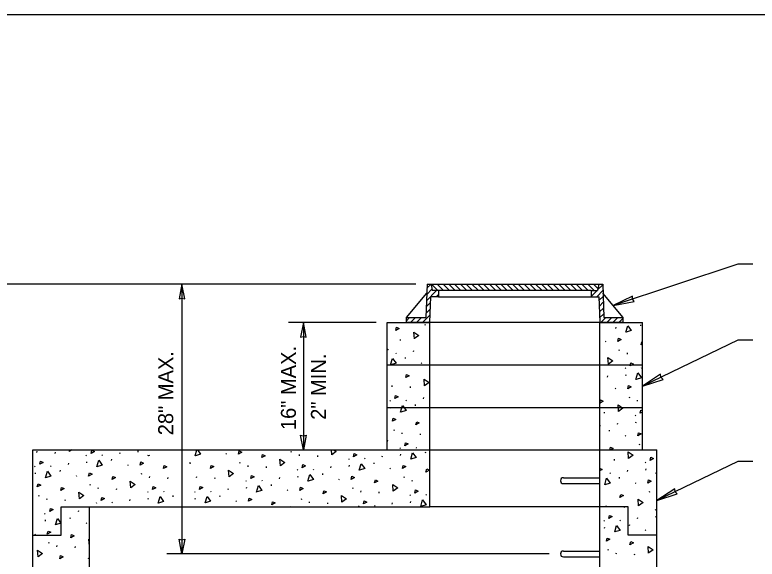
# Model space of a CAD drawing. Extents: x 99862 to 103151, y 100000 to 102076.
# Drawn here: x 100585 to 101377, y 101495 to 102076 of the extents above; entities that cross this region are included whole.
import ezdxf

# ---------------------------------------------------------------- set-up
doc = ezdxf.new("R2010")
doc.units = 0
for name, color, linetype in [('Level 1', 7, 'Continuous'), ('Level 15', 7, 'Continuous'), ('Level 16', 7, 'Continuous'), ('Level 17', 7, 'Continuous'), ('Level 18', 7, 'Continuous'), ('Level 20', 7, 'Continuous')]:
    doc.layers.add(name, color=color, linetype=linetype)

msp = doc.modelspace()

# ---------------------------------------------------------------- linework, layer by layer
at = {"layer": 'Level 1'}
for p, q in [((101024.66, 101788.47), (101023.36, 101752.82)), ((101024.19, 101777.48), (101029.83, 101783.11)), ((101024.46, 101784.09), (101028.81, 101788.47)), ((101024.66, 101788.47), (101030.11, 101788.47)), ((101028.86, 101788.47), (101030.11, 101781.67)), ((101029.31, 101788.47), (101036.1, 101781.67)), ((101030.11, 101788.47), (101207.63, 101788.47)), ((101035.48, 101788.47), (101042.27, 101781.67)), ((101041.65, 101788.47), (101048.44, 101781.67)), ((101047.82, 101788.47), (101054.62, 101781.67)), ((101053.99, 101788.47), (101060.79, 101781.67)), ((101060.16, 101788.47), (101066.96, 101781.67)), ((101066.33, 101788.47), (101073.14, 101781.67)), ((101072.5, 101788.47), (101079.31, 101781.67)), ((101078.68, 101788.47), (101085.49, 101781.67)), ((101084.85, 101788.47), (101091.66, 101781.67)), ((101091.02, 101788.47), (101097.83, 101781.67)), ((101097.2, 101788.47), (101104.01, 101781.67)), ((101103.37, 101788.47), (101110.18, 101781.67)), ((101109.55, 101788.47), (101116.35, 101781.67)), ((101115.72, 101788.47), (101122.52, 101781.67)), ((101121.89, 101788.47), (101128.69, 101781.67)), ((101128.07, 101788.47), (101134.86, 101781.67)), ((101134.24, 101788.47), (101141.03, 101781.67)), ((101140.42, 101788.47), (101147.21, 101781.67)), ((101146.59, 101788.47), (101153.38, 101781.67)), ((101152.76, 101788.47), (101159.55, 101781.67)), ((101158.94, 101788.47), (101165.73, 101781.67)), ((101165.11, 101788.47), (101171.9, 101781.67)), ((101171.29, 101788.47), (101178.08, 101781.67)), ((101177.46, 101788.47), (101184.25, 101781.67)), ((101183.63, 101788.47), (101190.42, 101781.67)), ((101189.81, 101788.47), (101196.6, 101781.67)), ((101195.98, 101788.47), (101202.77, 101781.67)), ((101202.15, 101788.47), (101206.8, 101783.83)), ((101207.63, 101788.47), (101206.41, 101781.67)), ((101206.46, 101782.23), (101211.95, 101787.67)), ((101207.63, 101788.47), (101211.91, 101788.47)), ((101211.91, 101788.47), (101213.12, 101752.82)), ((101002.58, 101752.82), (101024.25, 101778.73)), ((101023.97, 101770.81), (101034.81, 101781.67)), ((101036.96, 101781.67), (101030.11, 101781.67)), ((101034.4, 101774.91), (101036.96, 101777.38)), ((101036.96, 101781.67), (101036.96, 101774.91)), ((101199.61, 101781.67), (101036.96, 101781.67)), ((101199.61, 101781.67), (101206.41, 101781.67)), ((101199.61, 101781.67), (101199.61, 101774.91)), ((101199.61, 101775.38), (101205.89, 101781.67)), ((101205.53, 101774.91), (101212.1, 101781.52)), ((101208.23, 101771.22), (101212.33, 101775.28)), ((101233.9, 101752.82), (101212.19, 101778.73)), ((101023.73, 101764.24), (101028.34, 101768.8)), ((101027.6, 101747.75), (101028.57, 101774.91)), ((101037.05, 101774.91), (101028.57, 101774.91)), ((101036.96, 101774.91), (101199.61, 101774.91)), ((101199.61, 101774.91), (101208.13, 101774.91)), ((101209.12, 101747.75), (101208.13, 101774.91)), ((101208.46, 101765.08), (101212.56, 101769.13)), ((101023.55, 101757.61), (101028.12, 101762.19)), ((101208.65, 101758.89), (101212.8, 101762.98)), ((101002.58, 101752.82), (101023.36, 101752.82)), ((101002.58, 101747.75), (101002.58, 101752.82)), ((101002.58, 101749.47), (101006.02, 101752.82)), ((101007.27, 101747.75), (101012.41, 101752.82)), ((101013.72, 101747.75), (101018.79, 101752.82)), ((101020.15, 101747.75), (101027.83, 101755.57)), ((101208.88, 101752.78), (101213.03, 101756.79)), ((101210.33, 101747.75), (101215.4, 101752.82)), ((101213.12, 101752.82), (101233.9, 101752.82)), ((101216.7, 101747.75), (101221.79, 101752.82)), ((101223.13, 101747.75), (101228.21, 101752.82)), ((101229.48, 101747.75), (101233.9, 101752.18)), ((101233.9, 101747.75), (101233.9, 101752.82)), ((101002.58, 101747.75), (101027.6, 101747.75)), ((101026.48, 101747.75), (101027.6, 101748.92)), ((101027.6, 101747.75), (101209.12, 101747.75)), ((101209.12, 101747.75), (101233.9, 101747.75))]:
    msp.add_line(p, q, dxfattribs=at)
msp.add_lwpolyline([(99862, 99999.5), (103151, 99999.5), (103151, 102075.5), (99862, 102075.5)], close=True, dxfattribs=at)
at = {"layer": 'Level 15'}
for p, q in [((101356.07, 101809.67), (101223.05, 101765.78)), ((101372.07, 101809.67), (101356.07, 101809.67)), ((101012.66, 101788.47), (100352.49, 101788.47)), ((100763.18, 101788.47), (100763.18, 101500.81)), ((100970.21, 101747.72), (100876.72, 101747.72)), ((100892.72, 101747.72), (100892.72, 101611.69)), ((101356.07, 101728.7), (101254.43, 101679.7)), ((101372.07, 101728.7), (101356.07, 101728.7)), ((101356.07, 101599.38), (101269.59, 101557.69)), ((101372.07, 101599.38), (101356.07, 101599.38)), ((101154.85, 101500.81), (100747.18, 101500.81))]:
    msp.add_line(p, q, dxfattribs=at)
for points in [[(100763.18, 101788.47), (100760.1, 101772.75), (100763.18, 101773.48), (100766.27, 101772.75)], [(101223.05, 101765.78), (101245.66, 101770.09), (101243.72, 101772.6), (101243.79, 101775.76)], [(100892.72, 101747.72), (100889.63, 101731.99), (100892.72, 101732.72), (100895.8, 101731.99)], [(101254.43, 101679.7), (101276.29, 101686.93), (101274.04, 101689.16), (101273.7, 101692.31)], [(100892.72, 101611.69), (100889.63, 101627.42), (100892.72, 101626.69), (100895.8, 101627.42)], [(101269.59, 101557.69), (101291.45, 101564.92), (101289.2, 101567.15), (101288.86, 101570.3)], [(100763.18, 101500.81), (100760.1, 101516.54), (100763.18, 101515.81), (100766.27, 101516.54)]]:
    msp.add_lwpolyline(points, close=True, dxfattribs=at)
at = {"layer": 'Level 16'}
for p, q in [((101022.39, 101745.91), (101022.74, 101744.84)), ((101252.44, 101743.98), (101252.69, 101745.18)), ((101225.89, 101741.26), (101226.15, 101742.46)), ((100996.11, 101728.37), (100996.37, 101729.57)), ((101214.52, 101727.79), (101215.16, 101727.16)), ((100991.16, 101715.06), (100991.8, 101714.43)), ((101010.17, 101716.61), (101010.43, 101717.81)), ((101229.29, 101718.74), (101229.65, 101717.67)), ((101238.25, 101713.89), (101238.5, 101715.09)), ((101001.46, 101709.18), (101001.71, 101710.38)), ((101018.31, 101704.63), (101018.95, 101704.01)), ((101235.81, 101699.14), (101236.45, 101698.52)), ((101252.84, 101699.53), (101253.48, 101698.9)), ((101217.08, 101689.44), (101217.33, 101690.64)), ((101236.59, 101690.93), (101236.84, 101692.13)), ((100987.26, 101679.09), (100987.52, 101680.29)), ((101006.81, 101678.04), (101007.06, 101679.24)), ((101225.22, 101677.46), (101225.86, 101676.83)), ((100984.83, 101664.35), (100985.47, 101663.72)), ((101001.86, 101664.73), (101002.5, 101664.11)), ((101020.87, 101666.29), (101021.13, 101667.49)), ((101239.99, 101668.41), (101240.34, 101667.34)), ((101248.94, 101663.56), (101249.2, 101664.76)), ((100985.61, 101656.14), (100985.86, 101657.34)), ((101012.16, 101658.86), (101012.41, 101660.05)), ((101213.71, 101650.87), (101213.97, 101652.07)), ((101246.51, 101648.82), (101247.15, 101648.19)), ((101247.29, 101640.61), (101247.54, 101641.81)), ((100989.01, 101633.61), (100989.36, 101632.54)), ((101209.11, 101637.23), (101209.41, 101636.93)), ((101219.06, 101631.68), (101219.31, 101632.88)), ((101227.77, 101639.11), (101228.03, 101640.31)), ((100997.96, 101628.77), (100998.21, 101629.97)), ((101017.5, 101627.71), (101017.76, 101628.91)), ((101235.91, 101627.13), (101236.55, 101626.51)), ((101250.69, 101618.08), (101251.04, 101617.01)), ((100608.48, 101609.1), (100608.74, 101610.3)), ((100628.03, 101608.05), (100628.28, 101609.25)), ((100696.87, 101607.94), (100697.12, 101609.14)), ((100716.38, 101609.43), (100716.63, 101610.63)), ((100879.45, 101610.33), (100879.81, 101609.26)), ((100995.52, 101614.02), (100996.16, 101613.39)), ((101012.56, 101614.4), (101013.2, 101613.78)), ((101022.85, 101608.53), (101023.11, 101609.73)), ((100660.82, 101606), (100661.46, 101605.37)), ((100677.86, 101606.38), (100678.5, 101605.76)), ((100688.15, 101600.51), (100688.4, 101601.71)), ((100809.91, 101607.73), (100810.55, 101607.11)), ((100888.41, 101605.48), (100888.66, 101606.68)), ((100907.95, 101604.43), (100908.21, 101605.62)), ((100940.75, 101602.37), (100941.39, 101601.75)), ((100957.78, 101602.76), (100958.42, 101602.14)), ((100976.79, 101604.32), (100977.05, 101605.51)), ((100996.3, 101605.81), (100996.56, 101607.01)), ((101224.41, 101600.54), (101224.66, 101601.74)), ((100606.05, 101594.36), (100606.69, 101593.73)), ((100623.08, 101594.74), (100623.72, 101594.12)), ((100642.09, 101596.3), (100642.35, 101597.5)), ((100661.6, 101597.79), (100661.86, 101598.99)), ((100705.01, 101595.96), (100705.65, 101595.33)), ((100824.68, 101598.68), (100825.03, 101597.61)), ((100833.63, 101593.84), (100833.89, 101595.04)), ((100853.18, 101592.78), (100853.43, 101593.98)), ((100922.01, 101592.67), (100922.27, 101593.87)), ((100941.53, 101594.17), (100941.78, 101595.36)), ((100968.08, 101596.89), (100968.33, 101598.08)), ((101257.2, 101598.49), (101257.84, 101597.86)), ((100606.83, 101586.15), (100607.08, 101587.35)), ((100633.38, 101588.87), (100633.63, 101590.06)), ((100719.78, 101586.91), (100720.13, 101585.84)), ((100885.97, 101590.73), (100886.61, 101590.11)), ((100903.01, 101591.12), (100903.65, 101590.49)), ((100913.3, 101585.24), (100913.55, 101586.44)), ((100984.93, 101592.33), (100985.57, 101591.71)), ((101219.46, 101587.23), (101220.1, 101586.61)), ((101238.47, 101588.79), (101238.73, 101589.98)), ((101257.98, 101590.28), (101258.24, 101591.48)), ((100650.23, 101584.31), (100650.87, 101583.69)), ((100728.73, 101582.06), (100728.99, 101583.26)), ((100748.28, 101581.01), (100748.53, 101582.21)), ((100778.86, 101582.19), (100779.11, 101583.39)), ((100798.4, 101581.14), (100798.66, 101582.34)), ((100831.19, 101579.09), (100831.83, 101578.46)), ((100848.23, 101579.48), (100848.87, 101578.85)), ((100867.24, 101581.03), (100867.49, 101582.23)), ((100886.75, 101582.52), (100887.01, 101583.72)), ((100930.16, 101580.69), (100930.8, 101580.07)), ((100999.7, 101583.28), (101000.06, 101582.21)), ((101008.66, 101578.44), (101008.91, 101579.64)), ((101229.76, 101581.35), (101230.01, 101582.55)), ((100665, 101575.26), (100665.36, 101574.19)), ((100673.96, 101570.42), (100674.21, 101571.62)), ((100693.5, 101569.36), (100693.76, 101570.56)), ((100812.46, 101569.39), (100812.72, 101570.59)), ((100831.97, 101570.88), (100832.23, 101572.08)), ((100858.52, 101573.6), (100858.78, 101574.8)), ((100944.93, 101571.64), (100945.28, 101570.57)), ((101246.61, 101576.8), (101247.25, 101576.18)), ((100610.23, 101563.62), (100610.58, 101562.55)), ((100726.3, 101567.31), (100726.94, 101566.69)), ((100743.33, 101567.7), (100743.97, 101567.08)), ((100753.63, 101561.82), (100753.88, 101563.02)), ((100776.42, 101567.45), (100777.06, 101566.82)), ((100793.45, 101567.83), (100794.09, 101567.21)), ((100803.75, 101561.96), (100804, 101563.15)), ((100875.38, 101569.05), (100876.02, 101568.42)), ((100953.88, 101566.8), (100954.14, 101568)), ((100973.43, 101565.74), (100973.68, 101566.94)), ((101006.22, 101563.69), (101006.86, 101563.07)), ((101023.26, 101564.08), (101023.9, 101563.45)), ((101261.38, 101567.75), (101261.74, 101566.68)), ((100619.18, 101558.78), (100619.43, 101559.98)), ((100638.72, 101557.72), (100638.98, 101558.92)), ((100671.52, 101555.67), (100672.16, 101555.05)), ((100688.55, 101556.06), (100689.19, 101555.43)), ((100707.56, 101557.61), (100707.82, 101558.81)), ((100727.08, 101559.1), (100727.33, 101560.3)), ((100777.2, 101559.24), (100777.45, 101560.44)), ((100820.6, 101557.4), (100821.24, 101556.78)), ((100890.15, 101560), (100890.51, 101558.93)), ((100899.11, 101555.15), (100899.36, 101556.35)), ((100918.65, 101554.1), (100918.91, 101555.3)), ((100987.49, 101553.99), (100987.74, 101555.19)), ((101007, 101555.48), (101007.26, 101556.68)), ((100652.79, 101545.97), (100653.04, 101547.17)), ((100699.05, 101551.14), (100699.1, 101551.38)), ((100951.44, 101552.05), (100952.08, 101551.42)), ((100968.48, 101552.43), (100969.12, 101551.81)), ((101215.56, 101551.27), (101215.82, 101552.46)), ((101235.11, 101550.21), (101235.36, 101551.41)), ((101267.9, 101548.16), (101268.54, 101547.54)), ((100616.74, 101544.03), (100617.38, 101543.4)), ((100633.78, 101544.41), (100634.42, 101543.79)), ((100644.07, 101538.54), (100644.33, 101539.74)), ((101249.17, 101538.46), (101249.43, 101539.66)), ((101268.68, 101539.95), (101268.94, 101541.15)), ((100617.52, 101535.82), (100617.78, 101537.02)), ((100660.93, 101533.99), (100661.57, 101533.36)), ((101213.12, 101536.52), (101213.76, 101535.89)), ((101230.16, 101536.9), (101230.8, 101536.28)), ((101240.46, 101531.03), (101240.71, 101532.23)), ((100606.15, 101522.34), (100606.79, 101521.72)), ((101213.9, 101528.31), (101214.16, 101529.51)), ((101257.31, 101526.48), (101257.95, 101525.85)), ((100620.92, 101513.29), (100621.28, 101512.22)), ((100629.88, 101508.45), (100630.13, 101509.65)), ((100649.42, 101507.39), (100649.68, 101508.59)), ((101217.31, 101505.78), (101217.66, 101504.71)), ((101226.26, 101500.94), (101226.51, 101502.14)), ((101245.8, 101499.88), (101246.06, 101501.08)), ((100663.48, 101495.64), (100663.74, 101496.84))]:
    msp.add_line(p, q, dxfattribs=at)
for points in [[(101236.72, 101737.21), (101238.69, 101744.11), (101242.46, 101738.94), (101236.84, 101737.24)], [(100991.31, 101739.1), (100992.13, 101742.45), (100994.94, 101741.15), (100991.31, 101739.1)], [(101011.17, 101730.26), (101010.66, 101737.41), (101015.97, 101733.84), (101011.28, 101730.32)], [(101227.96, 101727.34), (101228.77, 101730.69), (101231.59, 101729.38), (101227.96, 101727.34)], [(101252.99, 101723.57), (101253.81, 101726.92), (101254.43, 101726.63)], [(101254.43, 101724.38), (101252.99, 101723.57)], [(100982.21, 101719.19), (100983.16, 101718.75), (100982.21, 101718.22)], [(100985.74, 101702.42), (100987.7, 101709.31), (100991.47, 101704.14), (100985.86, 101702.44)], [(101218.07, 101703.08), (101217.56, 101710.24), (101222.87, 101706.66), (101218.18, 101703.15)], [(101241.2, 101701.18), (101242.02, 101704.53), (101244.84, 101703.22), (101241.2, 101701.18)], [(101002.01, 101688.78), (101002.82, 101692.13), (101005.64, 101690.82), (101002.01, 101688.78)], [(101247.42, 101686.88), (101249.38, 101693.78), (101253.15, 101688.61), (101247.54, 101686.91)], [(101021.87, 101679.93), (101021.36, 101687.08), (101026.67, 101683.51), (101021.98, 101679.99)], [(101238.66, 101677.01), (101239.47, 101680.36), (101242.29, 101679.06), (101238.66, 101677.01)], [(100990.22, 101666.38), (100991.03, 101669.73), (100993.85, 101668.42), (100990.22, 101666.38)], [(101209.11, 101662.4), (101209.73, 101664.95), (101212.54, 101663.65), (101209.11, 101661.71)], [(100996.44, 101652.09), (100998.4, 101658.98), (101002.17, 101653.81), (100996.56, 101652.11)], [(101228.77, 101652.75), (101228.26, 101659.91), (101233.57, 101656.33), (101228.88, 101652.82)], [(101251.9, 101650.85), (101252.71, 101654.2), (101254.43, 101653.41)], [(101254.43, 101652.27), (101251.9, 101650.85)], [(100987.68, 101642.21), (100988.49, 101645.56), (100991.31, 101644.26), (100987.68, 101642.21)], [(101012.71, 101638.45), (101013.52, 101641.8), (101016.34, 101640.49), (101012.71, 101638.45)], [(101249.36, 101626.68), (101250.17, 101630.03), (101252.99, 101628.73), (101249.36, 101626.68)], [(100982.21, 101621.79), (100982.59, 101621.54), (100982.21, 101621.26)], [(101000.92, 101616.05), (101001.73, 101619.4), (101004.55, 101618.1), (101000.92, 101616.05)], [(100643.09, 101609.94), (100642.96, 101611.69)], [(100645.45, 101611.69), (100643.2, 101610)], [(100666.22, 101608.03), (100667.03, 101611.38), (100669.85, 101610.08), (100666.22, 101608.03)], [(100777.33, 101605.52), (100779.09, 101611.69)], [(100779.82, 101611.69), (100783.07, 101607.24), (100777.45, 101605.54)], [(100823.35, 101607.29), (100824.16, 101610.63), (100826.98, 101609.33), (100823.35, 101607.29)], [(100923.01, 101606.31), (100922.63, 101611.69)], [(100925.14, 101611.69), (100927.81, 101609.89), (100923.12, 101606.38)], [(101219.61, 101611.28), (101220.42, 101614.63), (101223.24, 101613.32), (101219.61, 101611.28)], [(101239.47, 101602.43), (101238.96, 101609.58), (101244.27, 101606.01), (101239.58, 101602.49)], [(100727.21, 101605.38), (100727.5, 101606.42)], [(100728.54, 101605.78), (100727.33, 101605.41)], [(100848.38, 101603.52), (100849.19, 101606.87), (100852.01, 101605.56), (100848.38, 101603.52)], [(100868.24, 101594.67), (100867.73, 101601.82), (100873.04, 101598.25), (100868.34, 101594.73)], [(100946.14, 101604.41), (100946.95, 101607.76), (100949.78, 101606.45), (100946.14, 101604.41)], [(101007.13, 101601.76), (101009.1, 101608.66), (101012.87, 101603.49), (101007.25, 101601.79)], [(101262.6, 101600.52), (101263.41, 101603.87), (101266.23, 101602.57), (101262.6, 101600.52)], [(100611.44, 101596.39), (100612.25, 101599.74), (100615.07, 101598.43), (100611.44, 101596.39)], [(100672.43, 101593.74), (100674.4, 101600.64), (100678.17, 101595.47), (100672.55, 101593.77)], [(100718.45, 101595.51), (100719.26, 101598.86), (100722.08, 101597.55), (100718.45, 101595.51)], [(100743.48, 101591.74), (100744.29, 101595.09), (100747.11, 101593.79), (100743.48, 101591.74)], [(100771.12, 101598.19), (100772.2, 101597.69), (100771.12, 101597.08)], [(100793.6, 101591.88), (100794.42, 101595.23), (100797.23, 101593.92), (100793.6, 101591.88)], [(100891.37, 101592.77), (100892.18, 101596.12), (100895, 101594.81), (100891.37, 101592.77)], [(100952.36, 101590.12), (100954.32, 101597.01), (100958.09, 101591.84), (100952.48, 101590.14)], [(100998.37, 101591.89), (100999.18, 101595.24), (101002, 101593.93), (100998.37, 101591.89)], [(100617.66, 101582.1), (100619.62, 101588.99), (100623.39, 101583.82), (100617.78, 101582.12)], [(100663.67, 101583.87), (100664.48, 101587.22), (100667.3, 101585.91), (100663.67, 101583.87)], [(100813.46, 101583.03), (100812.95, 101590.18), (100818.26, 101586.61), (100813.57, 101583.09)], [(100897.58, 101578.47), (100899.55, 101585.37), (100903.32, 101580.2), (100897.7, 101578.5)], [(101023.4, 101588.12), (101024.22, 101591.47), (101027.03, 101590.16), (101023.4, 101588.12)], [(101209.1, 101592.01), (101211.46, 101590.92), (101209.1, 101589.6)], [(101268.81, 101586.23), (101269.59, 101588.96)], [(101269.59, 101586.45), (101268.93, 101586.26)], [(100688.7, 101580.1), (100689.52, 101583.45), (100692.33, 101582.14), (100688.7, 101580.1)], [(100708.56, 101571.25), (100708.05, 101578.41), (100713.36, 101574.83), (100708.67, 101571.32)], [(100836.59, 101581.12), (100837.4, 101584.47), (100840.22, 101583.17), (100836.59, 101581.12)], [(100943.6, 101580.24), (100944.41, 101583.59), (100947.23, 101582.29), (100943.6, 101580.24)], [(100968.63, 101576.48), (100969.44, 101579.83), (100972.26, 101578.52), (100968.63, 101576.48)], [(101214.04, 101574.59), (101216, 101581.48), (101219.77, 101576.31), (101214.16, 101574.61)], [(101260.05, 101576.36), (101260.86, 101579.71), (101263.69, 101578.4), (101260.05, 101576.36)], [(100608.9, 101572.22), (100609.71, 101575.57), (100612.53, 101574.27), (100608.9, 101572.22)], [(100633.93, 101568.46), (100634.74, 101571.81), (100637.56, 101570.5), (100633.93, 101568.46)], [(100731.69, 101569.35), (100732.5, 101572.7), (100735.32, 101571.39), (100731.69, 101569.35)], [(100781.81, 101569.48), (100782.63, 101572.83), (100785.45, 101571.52), (100781.81, 101569.48)], [(100842.8, 101566.83), (100844.77, 101573.73), (100848.54, 101568.56), (100842.93, 101566.86)], [(100888.82, 101568.6), (100889.63, 101571.95), (100892.45, 101570.64), (100888.82, 101568.6)], [(100988.49, 101567.63), (100987.98, 101574.78), (100993.29, 101571.21), (100988.59, 101567.69)], [(100653.78, 101559.61), (100653.27, 101566.76), (100658.59, 101563.19), (100653.89, 101559.67)], [(100737.91, 101555.06), (100739.87, 101561.95), (100743.64, 101556.78), (100738.03, 101555.08)], [(100788.03, 101555.19), (100789.99, 101562.08), (100793.76, 101556.91), (100788.15, 101555.21)], [(100913.85, 101564.83), (100914.67, 101568.18), (100917.48, 101566.88), (100913.85, 101564.83)], [(100933.71, 101555.99), (100933.2, 101563.14), (100938.51, 101559.57), (100933.82, 101556.05)], [(101011.62, 101565.72), (101012.43, 101569.07), (101015.25, 101567.77), (101011.62, 101565.72)], [(101230.31, 101560.95), (101231.12, 101564.3), (101233.94, 101562.99), (101230.31, 101560.95)], [(100676.91, 101557.7), (100677.73, 101561.06), (100680.55, 101559.75), (100676.91, 101557.7)], [(100834.05, 101556.96), (100834.85, 101560.31), (100837.68, 101559), (100834.05, 101556.96)], [(100859.08, 101553.19), (100859.89, 101556.54), (100862.71, 101555.24), (100859.08, 101553.19)], [(100956.84, 101554.08), (100957.65, 101557.43), (100960.47, 101556.13), (100956.84, 101554.08)], [(101017.83, 101551.43), (101019.8, 101558.33), (101023.57, 101553.16), (101017.95, 101551.46)], [(101250.17, 101552.1), (101249.66, 101559.25), (101254.97, 101555.68), (101250.28, 101552.16)], [(100622.14, 101546.06), (100622.95, 101549.41), (100625.77, 101548.11), (100622.14, 101546.06)], [(100878.45, 101551.14), (100878.42, 101551.5), (100878.96, 101551.14)], [(100628.35, 101531.77), (100630.32, 101538.67), (100634.09, 101533.5), (100628.47, 101531.8)], [(101218.52, 101538.55), (101219.33, 101541.9), (101222.15, 101540.6), (101218.52, 101538.55)], [(101224.73, 101524.26), (101226.7, 101531.15), (101230.47, 101525.98), (101224.86, 101524.28)], [(100619.59, 101521.9), (100620.4, 101525.25), (100623.22, 101523.94), (100619.59, 101521.9)], [(100644.62, 101518.13), (100645.44, 101521.48), (100648.25, 101520.17), (100644.62, 101518.13)], [(100664.48, 101509.28), (100663.97, 101516.44), (100664.59, 101516.02)], [(101215.98, 101514.39), (101216.79, 101517.74), (101219.61, 101516.43), (101215.98, 101514.39)], [(101241.01, 101510.62), (101241.82, 101513.97), (101244.64, 101512.66), (101241.01, 101510.62)], [(100664.59, 101509.35), (100664.59, 101509.35)], [(101260.86, 101501.77), (101260.35, 101508.93), (101265.66, 101505.35), (101260.97, 101501.84)], [(100609.71, 101497.64), (100609.2, 101504.79), (100614.51, 101501.22), (100609.81, 101497.7)], [(100632.84, 101495.73), (100633.65, 101499.08), (100636.47, 101497.78), (100632.84, 101495.73)]]:
    msp.add_lwpolyline(points, dxfattribs=at)
at = {"layer": 'Level 17'}
for p, q in [((100982.21, 101611.69), (100982.21, 101747.72)), ((100982.21, 101747.72), (101027.61, 101747.72)), ((101027.61, 101551.14), (101027.61, 101747.72)), ((101209.03, 101551.14), (101209.03, 101747.72)), ((101209.03, 101747.72), (101254.43, 101747.72)), ((101254.43, 101611.69), (101254.43, 101747.72)), ((100982.21, 101702.4), (101027.61, 101702.4)), ((101027.61, 101702.4), (101209.03, 101702.4)), ((101209.03, 101702.4), (101254.43, 101702.4)), ((100982.21, 101657.01), (101027.61, 101657.01)), ((101027.61, 101657.01), (101209.03, 101657.01)), ((101209.03, 101657.01), (101254.43, 101657.01)), ((100604.12, 101611.69), (101027.61, 101611.69)), ((100604.12, 100643.69), (100604.12, 101611.69)), ((101027.61, 101611.69), (101209.03, 101611.69)), ((101209.03, 101611.69), (101269.59, 101611.69)), ((101269.59, 100583.14), (101269.59, 101611.69)), ((100634.36, 101520.87), (100634.36, 101551.14)), ((100634.36, 101551.14), (100664.59, 101551.14)), ((100664.59, 101551.14), (101027.61, 101551.14)), ((100664.59, 100643.69), (100664.59, 101551.14)), ((101209.03, 101551.14), (101027.61, 101551.14)), ((101239.26, 101551.14), (101209.03, 101551.14)), ((101209.03, 100643.69), (101209.03, 101551.14)), ((101239.26, 101520.87), (101239.26, 101551.14)), ((100604.12, 101520.87), (100634.36, 101520.87)), ((101269.5, 101520.87), (101239.26, 101520.87))]:
    msp.add_line(p, q, dxfattribs=at)
at = {"layer": 'Level 18'}
for p, q in [((101169.97, 101582.03), (101209.03, 101582.03)), ((101169.97, 101575.79), (101209.03, 101575.79)), ((101169.97, 101503.94), (101209.03, 101503.94)), ((101169.97, 101497.69), (101209.03, 101497.69))]:
    msp.add_line(p, q, dxfattribs=at)
for centre in [(101169.97, 101578.91), (101169.97, 101500.81)]:
    msp.add_arc(centre, 3.12, 90, 270, dxfattribs=at)

# ---------------------------------------------------------------- texts
at = {"layer": 'Level 20'}
for s, p in [('16" MAX.', (100884.72, 101632.87)), ('28" MAX.', (100753.81, 101627.34)), ('2" MIN.', (100916.72, 101643.8))]:
    msp.add_text(s, height=16, rotation=90, dxfattribs=at).set_placement(p)

doc.saveas('drawing.dxf')
